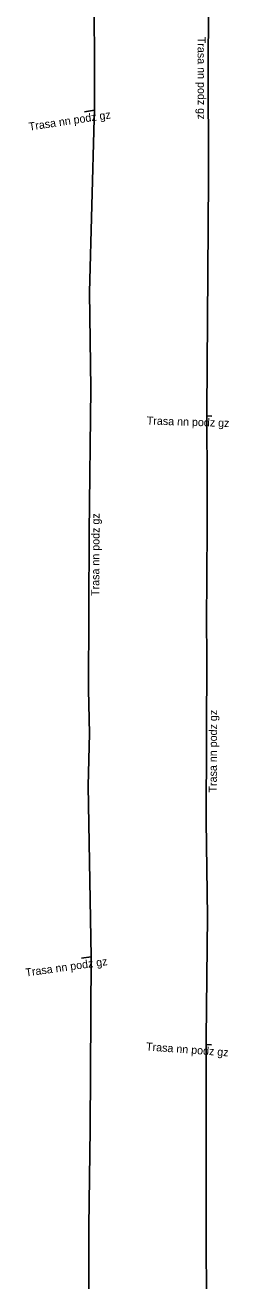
# Model space of a CAD drawing. Extents: x -747038 to -746494, y -1019526 to -1019195.
# Drawn here: x -746568.6 to -746555.9, y -1019436.6 to -1019358.2 of the extents above; entities that cross this region are included whole.
import ezdxf

# ---------------------------------------------------------------- set-up
doc = ezdxf.new("R2010")
doc.units = 0
doc.layers.add('Popiskový text - Ostatní atributy Trasy', color=7, linetype='Continuous')
doc.layers.add('Spojnice NN', color=7, linetype='Continuous')

msp = doc.modelspace()

# ---------------------------------------------------------------- linework, layer by layer
at = {"layer": 'Spojnice NN'}
for points in [[(-746564.254, -1019363.507), (-746564.274, -1019354.271), (-746564.282, -1019348.238), (-746564.22, -1019336.754), (-746564.27, -1019327.489), (-746564.324, -1019321.576), (-746564.379, -1019312.045), (-746564.32, -1019310.35)], [(-746557.117, -1019343.011), (-746557.043, -1019349.103), (-746557.102, -1019355.04), (-746557.159, -1019360.355), (-746557.133, -1019367.749), (-746557.167, -1019373.702), (-746557.239, -1019382.311), (-746557.241, -1019382.6)], [(-746564.254, -1019363.507), (-746564.878, -1019363.601)], [(-746564.466, -1019416.4), (-746564.656, -1019405.701), (-746564.568, -1019402.442), (-746564.635, -1019399.719), (-746564.589, -1019389.889), (-746564.481, -1019380.897), (-746564.565, -1019374.865), (-746564.269, -1019364.033), (-746564.254, -1019363.507)], [(-746557.241, -1019382.6), (-746557.231, -1019383.961), (-746557.206, -1019385.474), (-746557.206, -1019389.615), (-746557.247, -1019395.53), (-746557.228, -1019397.485), (-746557.268, -1019407.921), (-746557.184, -1019413.867), (-746557.27, -1019421.485), (-746557.274, -1019421.864)], [(-746557.241, -1019382.6), (-746556.919, -1019382.61)], [(-746564.466, -1019416.4), (-746565.069, -1019416.485)], [(-746564.706, -1019469.195), (-746564.751, -1019467.691), (-746564.606, -1019456.503), (-746564.633, -1019450.473), (-746564.606, -1019446.394), (-746564.61, -1019433.246), (-746564.524, -1019427.17), (-746564.466, -1019416.4)], [(-746557.274, -1019421.864), (-746557.286, -1019424.516), (-746557.268, -1019428.644), (-746557.278, -1019434.57), (-746557.248, -1019437.246), (-746557.219, -1019447.581), (-746557.261, -1019453.562), (-746557.35, -1019461.971), (-746557.355, -1019462.424)], [(-746557.274, -1019421.864), (-746556.949, -1019421.888)]]:
    msp.add_lwpolyline(points, dxfattribs=at)

# ---------------------------------------------------------------- texts
at = {"layer": 'Popiskový text - Ostatní atributy Trasy'}
for rotation, p in [(270.20147, (-746557.814, -1019358.914)), (8.56668, (-746568.319, -1019364.777)), (358.2212, (-746560.992, -1019383.134)), (89.73188, (-746563.957, -1019393.85)), (89.78039, (-746556.611, -1019406.129)), (8.02365, (-746568.533, -1019417.63)), (355.77659, (-746561.043, -1019422.238))]:
    msp.add_text('Trasa nn podz gz', height=0.5, rotation=rotation, dxfattribs=at).set_placement(p)

doc.saveas('drawing.dxf')
